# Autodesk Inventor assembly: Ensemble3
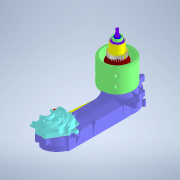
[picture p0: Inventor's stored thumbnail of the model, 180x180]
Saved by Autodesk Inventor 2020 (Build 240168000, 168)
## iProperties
Created: 2020-09
Part Number: Ensemble3
Document SubType Name: Assembly
Designer: Bruno
Author: Bruno
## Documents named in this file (5)
- D:\Téléchargements-2016-17\scoot_elec\Ensemble3.iam
- D:\Téléchargements-2016-17\scoot_elec\Transmission scoot elec.iam
- D:\Téléchargements-2016-17\scoot_elec\Ensemble-arbre-moteur.iam
- D:\Téléchargements-2016-17\scoot_elec\Ensemble-arbre-intermédiaire.iam
- D:\Téléchargements-2016-17\scoot_elec\pièces à assembler\Courroie crantée.ipt
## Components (4 placed, 4 different names)
1. Transmission scoot elec:1 [sub-assembly] — Logement:1, Logement:2
2. Ensemble-arbre-moteur:1 [sub-assembly] — Logement:1, Placage:1
3. Ensemble-arbre-intermédiaire:1 [sub-assembly] — Logement:2, Placage:2, Affleurement:1
4. Courroie crantée:1 — Placage:1, Placage:2, Affleurement:1
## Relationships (5: Insert 2, Mate 2, Flush 1)
- Logement:1 [Insert]: Transmission scoot elec:1 ↔ Ensemble-arbre-moteur:1
- Logement:2 [Insert]: Transmission scoot elec:1 ↔ Ensemble-arbre-intermédiaire:1
- Placage:1 [Mate]: Ensemble-arbre-moteur:1 ↔ Courroie crantée:1
- Placage:2 [Mate]: Ensemble-arbre-intermédiaire:1 ↔ Courroie crantée:1
- Affleurement:1 [Flush]: Ensemble-arbre-intermédiaire:1 ↔ Courroie crantée:1
